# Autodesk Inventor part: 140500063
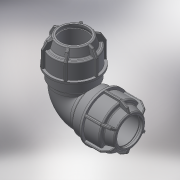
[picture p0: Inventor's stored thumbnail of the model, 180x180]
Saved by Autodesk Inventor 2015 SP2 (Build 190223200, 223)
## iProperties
Created: 2017-08
Part Number: 140500063
Material: Generic
Description: PLASSON L.14 90° ELBOW (SILVER) 63-63
Document SubType Name: Modeling
Designer: KIM
Density: 1 g/cm^3
Appearance: Default
Author: KIM
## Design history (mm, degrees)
derived "140500.ipt"
feature "Solid1::140500.ipt"
tag "TaggingFeature1"
body "Solid1"
other parameters: "d1" = 63, "d2" = 82, "d4" = 15 deg, "d5" = 54.12, "d6" = 17.8596, "d10" = 106, "d16" = 64.26, "d17" = 4.1, "d22" = 100.8, "d24" = 4.1, "d25" = 95.4, "d26" = 79.5, "d27" = 4.1, "d28" = 135 deg, "d29" = 2.46, "d31" = 3.15, "d46" = 150 deg, "d49" = 5.3, "d50" = 0, "d58" = 1.89, "d61" = 360 deg, "d63" = 56.7, "d80" = 90.72, "d81" = 5.04, "d84" = 4.1, "d112" = 119, "d113" = 1.19, "d115" = 90 deg, "d_" = 63, "E_" = 106, "A_" = 119, "l_" = 82
